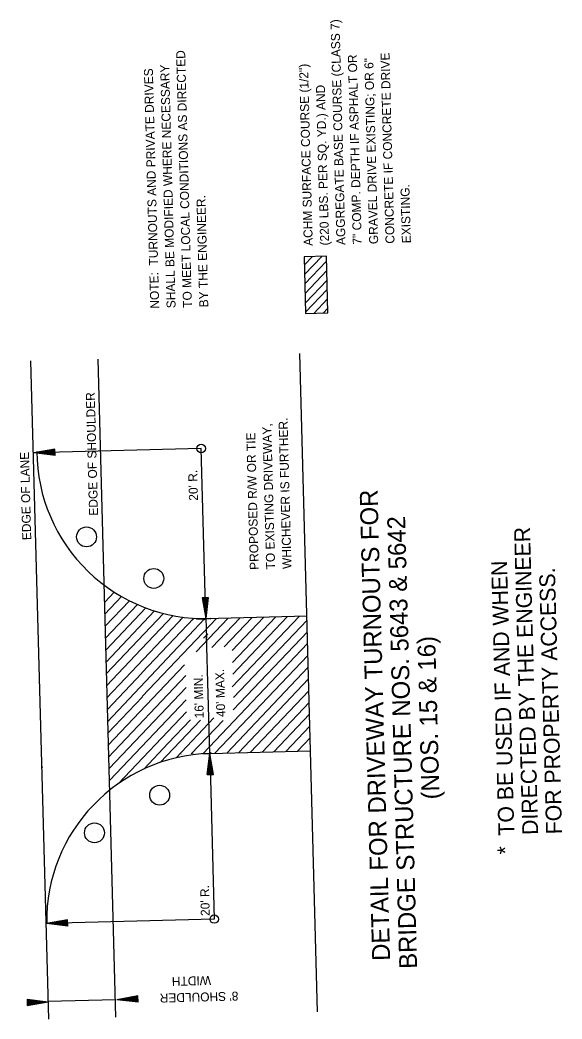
# Model space of a CAD drawing. Extents: x 1929624 to 1935547, y 596315 to 605721.
# Drawn here: x 1931746 to 1932155, y 604966 to 605721 of the extents above; entities that cross this region are included whole.
import ezdxf

# ---------------------------------------------------------------- set-up
doc = ezdxf.new("R2010")
doc.units = 0
for name, color, linetype in [('Default', 7, 'Continuous'), ('Level 47', 7, 'Continuous'), ('R_Annotation', 7, 'Continuous')]:
    doc.layers.add(name, color=color, linetype=linetype)

msp = doc.modelspace()

# ---------------------------------------------------------------- linework, layer by layer
at = {"layer": 'Default'}
for p, q in [((1931767.59, 604965.99), (1931754.24, 605463.11)), ((1931818.4, 604967.35), (1931805.06, 605464.47)), ((1931970.56, 604971.44), (1931957.22, 605468.56)), ((1931882.72, 605396.92), (1931756.42, 605393.53)), ((1931772.26, 605396.34), (1931756.42, 605393.53)), ((1931772.28, 605395.92), (1931759.13, 605393.6)), ((1931772.29, 605395.52), (1931761.84, 605393.67)), ((1931772.3, 605395.12), (1931764.47, 605393.74)), ((1931772.31, 605394.73), (1931767.19, 605393.81)), ((1931772.32, 605394.33), (1931769.83, 605393.89)), ((1931772.39, 605391.56), (1931772.26, 605396.34)), ((1931886.17, 605268.42), (1931882.72, 605396.92)), ((1931772.39, 605391.56), (1931756.42, 605393.53)), ((1931772.38, 605391.94), (1931759.13, 605393.6)), ((1931772.37, 605392.34), (1931761.84, 605393.67)), ((1931772.36, 605392.74), (1931764.47, 605393.74)), ((1931772.35, 605393.15), (1931767.19, 605393.81)), ((1931772.34, 605393.54), (1931769.83, 605393.89)), ((1931888.09, 605284.35), (1931883.36, 605284.22)), ((1931883.36, 605284.22), (1931886.17, 605268.42)), ((1931883.73, 605284.23), (1931886.1, 605271.07)), ((1931884.13, 605284.24), (1931886.03, 605273.81)), ((1931884.54, 605284.25), (1931885.96, 605276.43)), ((1931884.92, 605284.26), (1931885.88, 605279.13)), ((1931885.37, 605284.27), (1931885.81, 605281.77)), ((1931886.13, 605284.29), (1931885.81, 605281.77)), ((1931886.49, 605284.3), (1931885.88, 605279.13)), ((1931886.89, 605284.32), (1931885.96, 605276.43)), ((1931887.32, 605284.33), (1931886.03, 605273.81)), ((1931887.72, 605284.34), (1931886.1, 605271.07)), ((1931888.09, 605284.35), (1931886.17, 605268.42)), ((1931837.79, 605227.35), (1931877.1, 605268.7)), ((1931838.17, 605209.48), (1931894.21, 605268.43)), ((1931853.04, 605252.52), (1931869.15, 605269.48)), ((1931873.44, 605255.71), (1931885.3, 605268.19)), ((1931878.95, 605243.22), (1931903.12, 605268.66)), ((1931879.2, 605268.02), (1931886.45, 605268.22)), ((1931962.67, 605270.26), (1931886.18, 605268.21)), ((1931886.91, 605253.68), (1931886.5, 605268.79)), ((1931890.88, 605246.64), (1931912.03, 605268.9)), ((1931900.12, 605247.23), (1931920.95, 605269.14)), ((1931906.03, 605216.91), (1931956.6, 605270.1)), ((1931906.04, 605244.32), (1931929.86, 605269.38)), ((1931906.27, 605235.4), (1931938.77, 605269.62)), ((1931906.49, 605226.5), (1931947.7, 605269.86)), ((1931907.1, 605208.87), (1931962.62, 605267.28)), ((1931906.99, 605199.61), (1931962.86, 605258.38)), ((1931889.25, 605166.58), (1931886.84, 605256.18)), ((1931884.12, 605166.44), (1931963.1, 605249.51)), ((1931893.03, 605166.68), (1931963.34, 605240.62)), ((1931901.96, 605166.92), (1931963.57, 605231.72)), ((1931910.87, 605167.16), (1931963.81, 605222.84)), ((1931919.79, 605167.4), (1931964.05, 605213.94)), ((1931928.72, 605167.63), (1931964.29, 605205.07)), ((1931851.8, 605159.84), (1931882.12, 605191.72)), ((1931857.89, 605174.34), (1931874.59, 605191.92)), ((1931863.78, 605163.3), (1931892.36, 605193.38)), ((1931875.21, 605166.2), (1931899.28, 605191.51)), ((1931937.62, 605167.87), (1931964.53, 605196.19)), ((1931946.54, 605168.11), (1931964.77, 605187.29)), ((1931955.44, 605168.35), (1931965.01, 605178.42)), ((1931889.25, 605166.58), (1931965.27, 605168.62)), ((1931883.65, 605166.42), (1931889.58, 605166.58)), ((1931887.32, 605150.63), (1931889.25, 605166.58)), ((1931887.68, 605150.64), (1931889.32, 605163.89)), ((1931888.1, 605150.65), (1931889.39, 605161.18)), ((1931892.08, 605150.76), (1931889.25, 605166.58)), ((1931889.25, 605166.58), (1931892.61, 605041.5)), ((1931891.71, 605150.75), (1931889.32, 605163.89)), ((1931891.28, 605150.74), (1931889.39, 605161.18)), ((1931763.01, 605156.31), (1931762.31, 605156.52)), ((1931762.53, 605156.52), (1931763.01, 605156.31)), ((1931763.01, 605156.31), (1931762.78, 605156.53)), ((1931888.56, 605150.66), (1931889.46, 605158.53)), ((1931888.91, 605150.67), (1931889.54, 605155.83)), ((1931889.31, 605150.68), (1931889.61, 605153.18)), ((1931890.88, 605150.73), (1931889.46, 605158.53)), ((1931890.48, 605150.72), (1931889.54, 605155.83)), ((1931890.07, 605150.7), (1931889.61, 605153.18)), ((1931887.32, 605150.63), (1931892.08, 605150.76)), ((1931892.61, 605041.5), (1931766.06, 605038.1)), ((1931781.87, 605040.89), (1931766.06, 605038.1)), ((1931781.88, 605040.51), (1931768.73, 605038.18)), ((1931781.89, 605040.1), (1931771.46, 605038.25)), ((1931781.91, 605039.68), (1931774.08, 605038.32)), ((1931782, 605036.14), (1931781.87, 605040.89)), ((1931782, 605036.14), (1931766.06, 605038.1)), ((1931781.99, 605036.52), (1931768.73, 605038.18)), ((1931781.98, 605036.92), (1931771.46, 605038.25)), ((1931781.97, 605037.32), (1931774.08, 605038.32)), ((1931781.92, 605039.3), (1931776.79, 605038.39)), ((1931781.96, 605037.77), (1931776.79, 605038.39)), ((1931781.93, 605038.91), (1931779.44, 605038.46)), ((1931781.95, 605038.14), (1931779.44, 605038.46)), ((1931751.26, 604981.05), (1931767.24, 604979.08)), ((1931751.26, 604981.05), (1931751.39, 604976.27)), ((1931751.27, 604980.67), (1931764.59, 604979.01)), ((1931751.28, 604980.27), (1931761.86, 604978.94)), ((1931751.29, 604979.83), (1931759.2, 604978.87)), ((1931751.31, 604979.4), (1931756.49, 604978.79)), ((1931751.31, 604979.03), (1931753.9, 604978.72)), ((1931751.38, 604976.64), (1931764.59, 604979.01)), ((1931751.39, 604976.27), (1931767.24, 604979.08)), ((1931818.05, 604980.51), (1931767.23, 604979.15)), ((1931834.9, 604983.39), (1931819.06, 604980.57)), ((1931835.03, 604978.62), (1931819.06, 604980.57)), ((1931834.91, 604982.98), (1931821.77, 604980.64)), ((1931835.02, 604979.02), (1931821.77, 604980.64)), ((1931834.92, 604982.61), (1931824.47, 604980.71)), ((1931835.01, 604979.43), (1931824.47, 604980.71)), ((1931834.94, 604982.15), (1931827.11, 604980.79)), ((1931835, 604979.8), (1931827.11, 604980.79)), ((1931834.95, 604981.78), (1931829.83, 604980.86)), ((1931834.99, 604980.24), (1931829.83, 604980.86)), ((1931834.96, 604981.38), (1931832.46, 604980.93)), ((1931834.98, 604980.63), (1931832.46, 604980.93)), ((1931835.03, 604978.62), (1931834.9, 604983.39)), ((1931751.34, 604978.28), (1931753.9, 604978.72)), ((1931751.35, 604977.88), (1931756.49, 604978.79)), ((1931751.36, 604977.49), (1931759.2, 604978.87)), ((1931751.37, 604977.09), (1931761.86, 604978.94))]:
    msp.add_line(p, q, dxfattribs=at)
msp.add_lwpolyline([(1931961.58, 605498.82), (1931978.38, 605499.27), (1931977.23, 605542.12), (1931960.43, 605541.67)], close=True, dxfattribs=at)
for points in [[(1931960.59, 605535.43), (1931966.72, 605541.84)], [(1931960.79, 605528.32), (1931973.81, 605542.03)], [(1931960.98, 605521.18), (1931977.32, 605538.43)], [(1931961.17, 605514.04), (1931977.52, 605531.29)], [(1931961.36, 605506.93), (1931977.71, 605524.18)], [(1931961.55, 605499.81), (1931977.9, 605517.06)], [(1931967.73, 605498.98), (1931978.09, 605509.94)], [(1931974.88, 605499.18), (1931978.28, 605502.8)], [(1931809.99, 605280.88), (1931817.15, 605288.44)], [(1931809.97, 605271.7), (1931822.67, 605285.09)], [(1931810.21, 605262.68), (1931828.5, 605281.98)], [(1931810.41, 605253.64), (1931834.52, 605279.12)], [(1931810.65, 605244.62), (1931840.81, 605276.56)], [(1931810.89, 605235.63), (1931847.48, 605274.27)], [(1931811.07, 605226.6), (1931854.36, 605272.3)], [(1931837.44, 605245.25), (1931861.63, 605270.69)], [(1931866.8, 605267), (1931867.48, 605267.71)], [(1931875.9, 605267.27), (1931876.88, 605268.33)], [(1931884.9, 605267.53), (1931885.48, 605268.19)], [(1931889.41, 605268.06), (1931890.1, 605268.83)], [(1931811.48, 605208.63), (1931853.04, 605252.52)], [(1931811.95, 605190.53), (1931873.51, 605255.64)], [(1931884.43, 605253.61), (1931887.65, 605256.97)], [(1931811.28, 605217.59), (1931837.44, 605245.27)], [(1931812.34, 605172.51), (1931870.2, 605233.61)], [(1931811.71, 605199.53), (1931837.93, 605227.22)], [(1931812.54, 605163.52), (1931871.23, 605225.44)], [(1931813.36, 605155.14), (1931871.38, 605216.42)], [(1931812.12, 605181.53), (1931838.41, 605209.25)], [(1931813.6, 605146.18), (1931871.45, 605207.18)], [(1931819.96, 605143.65), (1931871.64, 605198.13)], [(1931839.31, 605154.82), (1931857.89, 605174.34)], [(1931867.4, 605165.99), (1931867.65, 605166.24)], [(1931876.38, 605166.23), (1931876.64, 605166.42)], [(1931885.31, 605166.4), (1931885.55, 605166.62)], [(1931889.67, 605166.73), (1931890.3, 605167.39)]]:
    msp.add_lwpolyline(points, dxfattribs=at)
for centre in [(1931882.71, 605396.9), (1931892.61, 605041.49)]:
    msp.add_circle(centre, 3.18, dxfattribs=at)
for centre, radius, start, end in [((1931885.52, 605395.23), 126.82, 180.29147, 271.53769), ((1931892.82, 605039.9), 126.76, 91.61408, 180.81198)]:
    msp.add_arc(centre, radius, start, end, dxfattribs=at)
at = {"layer": 'Level 47'}
for centre in [(1931796.16, 605330.15), (1931846.93, 605298.76), (1931851.33, 605135.05), (1931802.16, 605106.62)]:
    msp.add_circle(centre, 7.5, dxfattribs=at)

# ---------------------------------------------------------------- texts
at = {"layer": 'Default'}
for s, height, rotation, p in [('AGGREGATE BASE COURSE (CLASS 7)', 6.75, 91.53769, (1931991.67, 605550.7)), ('TO MEET LOCAL CONDITIONS AS DIRECTED', 6.75, 91.53769, (1931875.76, 605503.3)), ('7" COMP. DEPTH IF ASPHALT OR', 6.75, 91.53769, (1932004.01, 605551.03)), ('GRAVEL DRIVE EXISTING; OR 6"', 6.75, 91.53769, (1932016.36, 605551.37)), ('CONCRETE IF CONCRETE DRIVE', 6.75, 91.53769, (1932028.7, 605551.7)), ('NOTE:  TURNOUTS AND PRIVATE DRIVES', 6.75, 91.53769, (1931851.08, 605502.64)), ('SHALL BE MODIFIED WHERE NECESSARY', 6.75, 91.53769, (1931863.42, 605502.97)), ('ACHM SURFACE COURSE (1/2") ', 6.75, 91.53769, (1931966.99, 605550.04)), ('(220 LBS. PER SQ. YD.) AND ', 6.75, 91.53769, (1931979.33, 605550.37)), ('EXISTING.', 6.75, 91.53769, (1932041.04, 605552.03)), ('BY THE ENGINEER.', 6.75, 91.53769, (1931888.11, 605503.63)), ('EDGE OF SHOULDER', 6.75, 91.53769, (1931804.87, 605346.27)), ('WHICHEVER IS FURTHER.', 6.75, 91.53769, (1931950.93, 605306.01)), ('TO EXISTING DRIVEWAY,', 6.75, 91.53769, (1931938.58, 605305.68)), ('PROPOSED R/W OR TIE', 6.75, 91.53769, (1931926.24, 605305.35)), ('EDGE OF LANE', 6.75, 91.53769, (1931754.46, 605327.79)), ("20' R.", 6.75, 91.53769, (1931880.29, 605357.6)), ('DETAIL FOR DRIVEWAY TURNOUTS FOR', 13.5, 91.53769, (1932025.37, 605010.1)), ('BRIDGE STRUCTURE NOS. 5643 & 5642', 13.5, 91.53769, (1932045.81, 605004.05)), (' (NOS. 15 & 16)', 13.5, 91.53769, (1932062.8, 605127.03)), ("40' MAX.", 6.75, 91.53769, (1931900.96, 605194.19)), ("16' MIN.", 6.75, 91.53769, (1931884.69, 605193.14)), ("20' R.", 6.75, 91.53769, (1931889.23, 605043.94)), ('WIDTH', 6.75, 181.53769, (1931890.04, 604998.51)), ("8' SHOULDER", 6.75, 181.53769, (1931910.69, 604986.71))]:
    msp.add_text(s, height=height, rotation=rotation, dxfattribs=at).set_placement(p)
at = {"layer": 'R_Annotation'}
for s, p in [('DIRECTED BY THE ENGINEER', (1932137.16, 605105.2)), ('TO BE USED IF AND WHEN', (1932119.16, 605104.72)), ('FOR PROPERTY ACCESS.', (1932155.15, 605105.69)), ('*', (1932118.35, 605090.54))]:
    msp.add_text(s, height=12, rotation=91.53769, dxfattribs=at).set_placement(p)

doc.saveas('drawing.dxf')
